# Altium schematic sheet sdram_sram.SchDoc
size A4
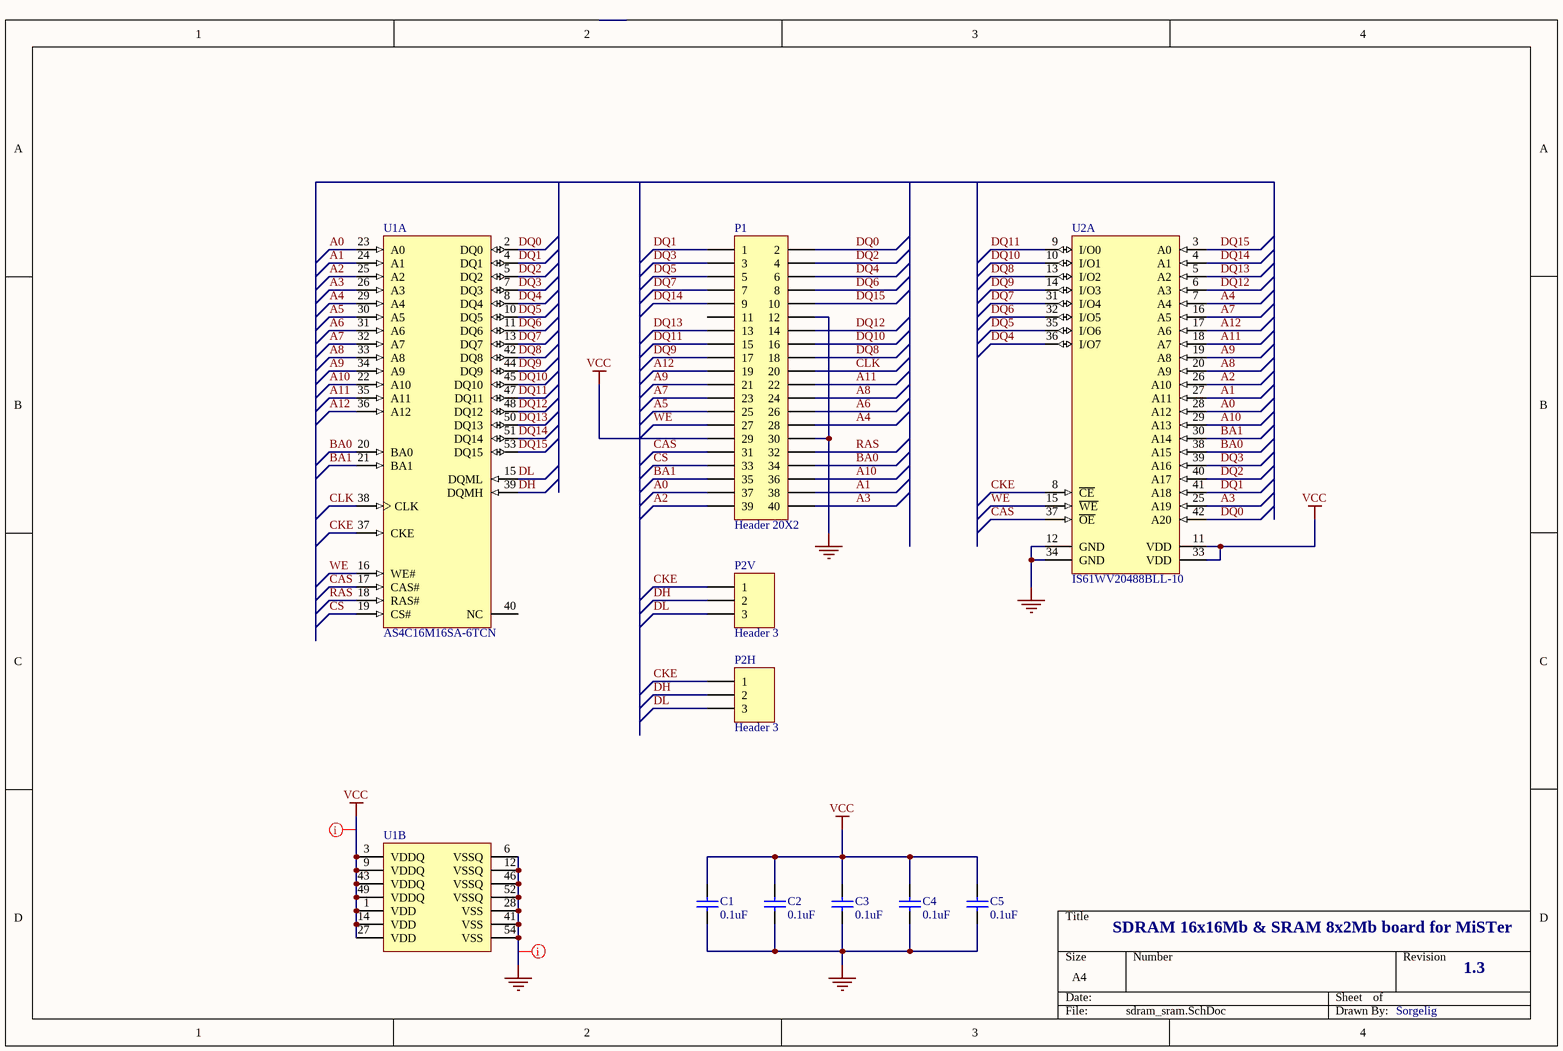
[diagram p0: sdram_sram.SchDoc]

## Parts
C1  value 0.1uF  [C0805]  (hidden comment: C0805)
C2  value 0.1uF  [C0805]  (hidden comment: C0805)
C3  value 0.1uF  [C0805]  (hidden comment: +)
C4  value 0.1uF  [C0805]  (hidden comment: C0805)
C5  value 0.1uF  [C0805]  (hidden comment: +)
P1  Header 20X2  [HDR20x2_90]
P2H  Header 3  [HDR1X3]
P2V  Header 3  [HDR1X3]
U1  AS4C16M16SA-6TCN  [TSOP54]  (parts A,B of 2)
U2  IS61WV20488BLL-10  [ISSI-TSOP-2-44_N]  (part A of 2)

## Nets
GND: C1.1 C2.1 C3.1 C4.1 C5.1 P1.12 P1.30 U1.6(VSSQ) U1.12(VSSQ) U1.28(VSS) U1.41(VSS) U1.46(VSSQ) U1.52(VSSQ) U1.54(VSS) U2.12(GND) U2.34(GND)
VCC: C1.2 C2.2 C3.2 C4.2 C5.2 P1.29 U1.1(VDD) U1.3(VDDQ) U1.9(VDDQ) U1.14(VDD) U1.27(VDD) U1.43(VDDQ) U1.49(VDDQ) U2.11(VDD) U2.33(VDD)
A0: P1.37 U1.23(A0) U2.28(A12)
A1: P1.38 U1.24(A1) U2.27(A11)
A2: P1.39 U1.25(A2) U2.26(A10)
A3: P1.40 U1.26(A3) U2.25(A19)
A4: P1.28 U1.29(A4) U2.7(A4)
A5: P1.25 U1.30(A5)
A6: P1.26 U1.31(A6)
A7: P1.23 U1.32(A7) U2.16(A5)
A8: P1.24 U1.33(A8) U2.20(A9)
A9: P1.21 U1.34(A9) U2.19(A8)
A10: P1.36 U1.22(A10) U2.29(A13)
A11: P1.22 U1.35(A11) U2.18(A7)
A12: P1.19 U1.36(A12) U2.17(A6)
BA0: P1.34 U1.20(BA0) U2.38(A15)
BA1: P1.35 U1.21(BA1) U2.30(A14)
CAS: P1.31 U1.17(CAS#) U2.37(~{OE})
CKE: P2H.1 P2V.1 U1.37(CKE) U2.8(~{CE})
CLK: P1.20 U1.38(CLK)
CS: P1.33 U1.19(CS#)
DH: P2H.2 P2V.2 U1.39(DQMH)
DL: P2H.3 P2V.3 U1.15(DQML)
DQ0: P1.2 U1.2(DQ0) U2.42(A20)
DQ1: P1.1 U1.4(DQ1) U2.41(A18)
DQ2: P1.4 U1.5(DQ2) U2.40(A17)
DQ3: P1.3 U1.7(DQ3) U2.39(A16)
DQ4: P1.6 U1.8(DQ4) U2.36(I/O7)
DQ5: P1.5 U1.10(DQ5) U2.35(I/O6)
DQ6: P1.8 U1.11(DQ6) U2.32(I/O5)
DQ7: P1.7 U1.13(DQ7) U2.31(I/O4)
DQ8: P1.18 U1.42(DQ8) U2.13(I/O2)
DQ9: P1.17 U1.44(DQ9) U2.14(I/O3)
DQ10: P1.16 U1.45(DQ10) U2.10(I/O1)
DQ11: P1.15 U1.47(DQ11) U2.9(I/O0)
DQ12: P1.14 U1.48(DQ12) U2.6(A3)
DQ13: P1.13 U1.50(DQ13) U2.5(A2)
DQ14: P1.9 U1.51(DQ14) U2.4(A1)
DQ15: P1.10 U1.53(DQ15) U2.3(A0)
RAS: P1.32 U1.18(RAS#)
WE: P1.27 U1.16(WE#) U2.15(~{WE})

Not connected (* = marked no-connect by the designer): P1 11; U1 40(NC)

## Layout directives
net class power: GND, VCC

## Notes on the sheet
- SDRAM 16x16Mb & SRAM 8x2Mb board for MiSTer
- 1.3
- Sorgelig

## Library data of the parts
C1-C5 = C0805: Ceramic Chip Capacitor - Standard; Note: Footprint corresponds to dimensions for bulk cassette packaging. This case size has tightened tolerances.
P1 = Header 20X2: Header, 20-Pin, Dual row
P2H P2V = Header 3: Header, 3-Pin
U1 = AS4C16M16SA-6TCN: 256Mb SDR SDRAM, 16Mb x 16, 6ns, 3.3V, 54-Pin TSOP; Manufacturer: Micron; PartNumber: MT48LC16M16A2P-6A; CL: CL = 3; Clock Rate: 167 MHz; Data Rate: PC133; Op. Temp.: 0C to +70C
U2 = IS61WV20488BLL-10TI: 16 M High Speed CMOS SRAM, 2 M x 8, -40 to 85 degC, 44-Pin SOP (TSOP-2-44); Manufacturer: Integrated Silicon Solution Inc (ISSI); Organization: 2M x 8; Packing: Tray / Tube; Speed (ns): 10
